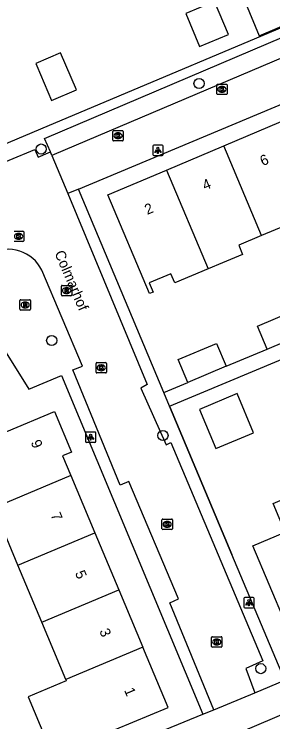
# Model space of a CAD drawing. Extents: x 157767 to 159171, y 387842 to 389425.
# Drawn here: x 158881 to 158906, y 388111.6 to 388179.9 of the extents above; entities that cross this region are included whole.
import ezdxf

# ---------------------------------------------------------------- set-up
doc = ezdxf.new("R2010")
doc.units = 0
for name, color, linetype in [('IMGEO_Boom', 7, 'Continuous'), ('IMGEO_Kolk', 7, 'Continuous'), ('IMGEO_Lichtpunt', 7, 'Continuous'), ('IMGEO_Muur', 7, 'Continuous'), ('IMGEO_Openbare_ruimte_label', 7, 'Continuous'), ('IMGEO_Pand', 7, 'Continuous'), ('IMGEO_Pand_nummerreeks', 7, 'Continuous'), ('IMGEO_Rijbaan_lokaal_open', 7, 'Continuous'), ('IMGEO_Rioolput', 7, 'Continuous'), ('IMGEO_Voetpad_open', 7, 'Continuous')]:
    doc.layers.add(name, color=color, linetype=linetype)

msp = doc.modelspace()

# ---------------------------------------------------------------- linework, layer by layer
at = {"layer": 'IMGEO_Boom'}
for centre in [(158898.833, 388173.23), (158883.577, 388166.9), (158884.584, 388148.404), (158895.347, 388139.23), (158904.8, 388116.715)]:
    msp.add_circle(centre, 0.489, dxfattribs=at)
at = {"layer": 'IMGEO_Kolk'}
for p, q in [((158900.55, 388172.235), (158900.55, 388173.087)), ((158900.625, 388173.161), (158901.477, 388173.161)), ((158901.038, 388172.941), (158901.063, 388172.941)), ((158901.551, 388173.087), (158901.551, 388172.235)), ((158901.477, 388172.161), (158900.625, 388172.161)), ((158901.061, 388172.381), (158901.036, 388172.381)), ((158890.498, 388167.753), (158890.498, 388168.605)), ((158890.573, 388168.679), (158891.425, 388168.679)), ((158890.986, 388168.459), (158891.011, 388168.459)), ((158891.499, 388168.605), (158891.499, 388167.753)), ((158891.425, 388167.679), (158890.573, 388167.679)), ((158891.009, 388167.899), (158890.984, 388167.899)), ((158880.954, 388158.964), (158881.806, 388158.964)), ((158881.367, 388158.744), (158881.392, 388158.744)), ((158881.88, 388158.89), (158881.88, 388158.038)), ((158881.806, 388157.964), (158880.954, 388157.964)), ((158881.39, 388158.184), (158881.365, 388158.184)), ((158888.875, 388145.342), (158888.875, 388146.194)), ((158888.95, 388146.268), (158889.802, 388146.268)), ((158889.876, 388146.194), (158889.876, 388145.342)), ((158889.386, 388145.488), (158889.361, 388145.488)), ((158889.363, 388146.048), (158889.388, 388146.048)), ((158889.802, 388145.268), (158888.95, 388145.268)), ((158895.326, 388131.158), (158896.178, 388131.158)), ((158895.251, 388130.232), (158895.251, 388131.084)), ((158895.739, 388130.938), (158895.764, 388130.938)), ((158896.252, 388131.084), (158896.252, 388130.232)), ((158896.178, 388130.158), (158895.326, 388130.158)), ((158895.762, 388130.378), (158895.737, 388130.378)), ((158900.047, 388118.866), (158900.047, 388119.718)), ((158900.122, 388119.792), (158900.974, 388119.792)), ((158900.535, 388119.572), (158900.56, 388119.572)), ((158901.048, 388119.718), (158901.048, 388118.866)), ((158900.558, 388119.012), (158900.533, 388119.012)), ((158900.974, 388118.792), (158900.122, 388118.792))]:
    msp.add_line(p, q, dxfattribs=at)
for points in [[(158900.55, 388172.235), (158900.55, 388173.087)], [(158900.625, 388173.161), (158901.477, 388173.161)], [(158900.871, 388172.861), (158900.994, 388172.861), (158900.994, 388172.71), (158901.124, 388172.861), (158901.288, 388172.861), (158901.142, 388172.71), (158901.295, 388172.461), (158901.143, 388172.461), (158901.058, 388172.625), (158900.994, 388172.558), (158900.994, 388172.461), (158900.871, 388172.461), (158900.871, 388172.861)], [(158901.551, 388173.087), (158901.551, 388172.235)], [(158901.477, 388172.161), (158900.625, 388172.161)], [(158890.498, 388167.753), (158890.498, 388168.605)], [(158890.573, 388168.679), (158891.425, 388168.679)], [(158890.819, 388168.379), (158890.942, 388168.379), (158890.942, 388168.228), (158891.072, 388168.379), (158891.236, 388168.379), (158891.09, 388168.228), (158891.243, 388167.979), (158891.091, 388167.979), (158891.006, 388168.143), (158890.942, 388168.076), (158890.942, 388167.979), (158890.819, 388167.979), (158890.819, 388168.379)], [(158891.499, 388168.605), (158891.499, 388167.753)], [(158891.425, 388167.679), (158890.573, 388167.679)], [(158880.954, 388158.964), (158881.806, 388158.964)], [(158881.2, 388158.664), (158881.323, 388158.664), (158881.323, 388158.513), (158881.453, 388158.664), (158881.617, 388158.664), (158881.471, 388158.513), (158881.624, 388158.264), (158881.472, 388158.264), (158881.387, 388158.428), (158881.323, 388158.361), (158881.323, 388158.264), (158881.2, 388158.264), (158881.2, 388158.664)], [(158881.88, 388158.89), (158881.88, 388158.038)], [(158881.806, 388157.964), (158880.954, 388157.964)], [(158888.875, 388145.342), (158888.875, 388146.194)], [(158888.95, 388146.268), (158889.802, 388146.268)], [(158889.876, 388146.194), (158889.876, 388145.342)], [(158889.196, 388145.968), (158889.319, 388145.968), (158889.319, 388145.817), (158889.449, 388145.968), (158889.613, 388145.968), (158889.467, 388145.817), (158889.62, 388145.568), (158889.468, 388145.568), (158889.383, 388145.732), (158889.319, 388145.665), (158889.319, 388145.568), (158889.196, 388145.568), (158889.196, 388145.968)], [(158889.802, 388145.268), (158888.95, 388145.268)], [(158895.326, 388131.158), (158896.178, 388131.158)], [(158895.251, 388130.232), (158895.251, 388131.084)], [(158895.572, 388130.858), (158895.695, 388130.858), (158895.695, 388130.707), (158895.825, 388130.858), (158895.989, 388130.858), (158895.843, 388130.707), (158895.996, 388130.458), (158895.844, 388130.458), (158895.759, 388130.622), (158895.695, 388130.555), (158895.695, 388130.458), (158895.572, 388130.458), (158895.572, 388130.858)], [(158896.252, 388131.084), (158896.252, 388130.232)], [(158896.178, 388130.158), (158895.326, 388130.158)], [(158900.047, 388118.866), (158900.047, 388119.718)], [(158900.122, 388119.792), (158900.974, 388119.792)], [(158901.048, 388119.718), (158901.048, 388118.866)], [(158900.368, 388119.492), (158900.491, 388119.492), (158900.491, 388119.341), (158900.621, 388119.492), (158900.785, 388119.492), (158900.639, 388119.341), (158900.792, 388119.092), (158900.64, 388119.092), (158900.555, 388119.256), (158900.491, 388119.189), (158900.491, 388119.092), (158900.368, 388119.092), (158900.368, 388119.492)], [(158900.974, 388118.792), (158900.122, 388118.792)]]:
    msp.add_lwpolyline(points, dxfattribs=at)
for centre, start, end in [((158900.627, 388173.085), 91.55205, 178.44795), ((158900.627, 388173.085), 91.55205, 178.44795), ((158901.475, 388173.085), 1.55205, 88.44795), ((158901.475, 388173.085), 1.55205, 88.44795), ((158900.627, 388172.237), 181.55205, 268.44795), ((158900.627, 388172.237), 181.55205, 268.44795), ((158901.475, 388172.237), 271.55205, 358.44795), ((158901.475, 388172.237), 271.55205, 358.44795), ((158890.575, 388168.603), 91.55205, 178.44795), ((158890.575, 388168.603), 91.55205, 178.44795), ((158891.423, 388168.603), 1.55205, 88.44795), ((158891.423, 388168.603), 1.55205, 88.44795), ((158890.575, 388167.755), 181.55205, 268.44795), ((158890.575, 388167.755), 181.55205, 268.44795), ((158891.423, 388167.755), 271.55205, 358.44795), ((158891.423, 388167.755), 271.55205, 358.44795), ((158881.804, 388158.888), 1.55205, 88.44795), ((158881.804, 388158.888), 1.55205, 88.44795), ((158881.804, 388158.04), 271.55205, 358.44795), ((158881.804, 388158.04), 271.55205, 358.44795), ((158888.952, 388146.192), 91.55205, 178.44795), ((158888.952, 388146.192), 91.55205, 178.44795), ((158889.8, 388146.192), 1.55205, 88.44795), ((158889.8, 388146.192), 1.55205, 88.44795), ((158888.952, 388145.344), 181.55205, 268.44795), ((158888.952, 388145.344), 181.55205, 268.44795), ((158889.8, 388145.344), 271.55205, 358.44795), ((158889.8, 388145.344), 271.55205, 358.44795), ((158895.328, 388131.082), 91.55205, 178.44795), ((158895.328, 388131.082), 91.55205, 178.44795), ((158896.176, 388131.082), 1.55205, 88.44795), ((158896.176, 388131.082), 1.55205, 88.44795), ((158895.328, 388130.234), 181.55205, 268.44795), ((158895.328, 388130.234), 181.55205, 268.44795), ((158896.176, 388130.234), 271.55205, 358.44795), ((158896.176, 388130.234), 271.55205, 358.44795), ((158900.124, 388119.716), 91.55205, 178.44795), ((158900.124, 388119.716), 91.55205, 178.44795), ((158900.972, 388119.716), 1.55205, 88.44795), ((158900.972, 388119.716), 1.55205, 88.44795), ((158900.124, 388118.868), 181.55205, 268.44795), ((158900.124, 388118.868), 181.55205, 268.44795), ((158900.972, 388118.868), 271.55205, 358.44795), ((158900.972, 388118.868), 271.55205, 358.44795)]:
    msp.add_arc(centre, 0.0765, start, end, dxfattribs=at)
for centre, major_axis, ratio, start_param, end_param in [((158901.037, 388172.661), (-0.387, 0.002), 0.722429, 4.712389, 7.853982), ((158901.062, 388172.661), (-0.39, 0.002), 0.717154, 1.570796, 4.712389), ((158890.985, 388168.179), (-0.387, 0.002), 0.722429, 4.712389, 7.853982), ((158891.01, 388168.179), (-0.39, 0.002), 0.717154, 1.570796, 4.712389), ((158881.366, 388158.464), (-0.387, 0.002), 0.722429, 4.712389, 7.853982), ((158881.391, 388158.464), (-0.39, 0.002), 0.717154, 1.570796, 4.712389), ((158889.362, 388145.768), (-0.387, 0.002), 0.722429, 4.712389, 7.853982), ((158889.387, 388145.768), (-0.39, 0.002), 0.717154, 1.570796, 4.712389), ((158895.738, 388130.658), (-0.387, 0.002), 0.722429, 4.712389, 7.853982), ((158895.763, 388130.658), (-0.39, 0.002), 0.717154, 1.570796, 4.712389), ((158900.534, 388119.292), (-0.387, 0.002), 0.722429, 4.712389, 7.853982), ((158900.559, 388119.292), (-0.39, 0.002), 0.717154, 1.570796, 4.712389)]:
    msp.add_ellipse(centre, major_axis=major_axis, ratio=ratio, start_param=start_param, end_param=end_param, dxfattribs=at)
at = {"layer": 'IMGEO_Lichtpunt'}
for p, q in [((158894.355, 388167.175), (158894.355, 388166.368)), ((158894.355, 388167.175), (158894.355, 388166.368)), ((158895.257, 388167.27), (158894.449, 388167.27)), ((158895.257, 388167.27), (158894.449, 388167.27)), ((158895.351, 388166.368), (158895.351, 388167.175)), ((158895.351, 388166.368), (158895.351, 388167.175)), ((158894.449, 388166.274), (158895.257, 388166.274)), ((158894.449, 388166.274), (158895.257, 388166.274)), ((158887.854, 388139.472), (158887.854, 388138.665)), ((158887.854, 388139.472), (158887.854, 388138.665)), ((158888.756, 388139.567), (158887.948, 388139.567)), ((158888.756, 388139.567), (158887.948, 388139.567)), ((158888.85, 388138.665), (158888.85, 388139.472)), ((158888.85, 388138.665), (158888.85, 388139.472)), ((158887.948, 388138.571), (158888.756, 388138.571)), ((158887.948, 388138.571), (158888.756, 388138.571)), ((158903.155, 388123.48), (158903.155, 388122.673)), ((158903.155, 388123.48), (158903.155, 388122.673)), ((158904.057, 388123.575), (158903.249, 388123.575)), ((158904.057, 388123.575), (158903.249, 388123.575)), ((158904.151, 388122.673), (158904.151, 388123.48)), ((158904.151, 388122.673), (158904.151, 388123.48)), ((158903.249, 388122.579), (158904.057, 388122.579)), ((158903.249, 388122.579), (158904.057, 388122.579))]:
    msp.add_line(p, q, dxfattribs=at)
for points in [[(158894.729, 388166.839), (158894.768, 388166.811), (158894.58, 388166.549), (158894.542, 388166.576), (158894.729, 388166.839)], [(158894.831, 388166.791), (158894.878, 388166.791), (158894.878, 388166.469), (158894.831, 388166.469), (158894.831, 388166.791)], [(158894.941, 388166.811), (158894.979, 388166.838), (158895.166, 388166.576), (158895.127, 388166.548), (158894.941, 388166.811)], [(158888.228, 388139.136), (158888.267, 388139.108), (158888.079, 388138.846), (158888.041, 388138.873), (158888.228, 388139.136)], [(158888.33, 388139.088), (158888.377, 388139.088), (158888.377, 388138.766), (158888.33, 388138.766), (158888.33, 388139.088)], [(158888.44, 388139.108), (158888.478, 388139.135), (158888.665, 388138.873), (158888.626, 388138.845), (158888.44, 388139.108)], [(158903.529, 388123.144), (158903.568, 388123.116), (158903.38, 388122.854), (158903.342, 388122.881), (158903.529, 388123.144)], [(158903.631, 388123.096), (158903.678, 388123.096), (158903.678, 388122.774), (158903.631, 388122.774), (158903.631, 388123.096)], [(158903.741, 388123.116), (158903.779, 388123.143), (158903.966, 388122.881), (158903.927, 388122.853), (158903.741, 388123.116)]]:
    msp.add_lwpolyline(points, dxfattribs=at)
for centre in [(158894.854, 388166.973), (158888.353, 388139.27), (158903.654, 388123.278)]:
    msp.add_circle(centre, 0.0994, dxfattribs=at)
for centre, start, end in [((158894.449, 388167.175), 90, 180), ((158894.449, 388167.175), 90, 180), ((158895.257, 388167.175), 0, 90), ((158895.257, 388167.175), 0, 90), ((158894.449, 388166.368), 180, 270), ((158894.449, 388166.368), 180, 270), ((158895.257, 388166.368), 270, 0), ((158895.257, 388166.368), 270, 360), ((158887.948, 388139.472), 90, 180), ((158887.948, 388139.472), 90, 180), ((158888.756, 388139.472), 0, 90), ((158888.756, 388139.472), 0, 90), ((158887.948, 388138.665), 180, 270), ((158887.948, 388138.665), 180, 270), ((158888.756, 388138.665), 270, 0), ((158888.756, 388138.665), 270, 360), ((158903.249, 388123.48), 90, 180), ((158903.249, 388123.48), 90, 180), ((158904.057, 388123.48), 0, 90), ((158904.057, 388123.48), 0, 90), ((158903.249, 388122.673), 180, 270), ((158903.249, 388122.673), 180, 270), ((158904.057, 388122.673), 270, 0), ((158904.057, 388122.673), 270, 360)]:
    msp.add_arc(centre, 0.0946, start, end, dxfattribs=at)
at = {"layer": 'IMGEO_Muur'}
msp.add_lwpolyline([(158895.992, 388142.055), (158902.018, 388127.735)], dxfattribs=at)
at = {"layer": 'IMGEO_Pand'}
for points in [[(158903.309, 388181.021), (158904.65, 388177.841), (158908.366, 388179.409), (158907.024, 388182.589), (158903.309, 388181.021)], [(158897.564, 388179.993), (158898.892, 388176.812), (158901.669, 388177.971), (158900.341, 388181.153), (158897.564, 388179.993)], [(158885.44, 388176.196), (158883.046, 388175.166), (158883.146, 388174.933), (158884.581, 388171.599), (158886.975, 388172.629), (158885.44, 388176.196)], [(158901.229, 388167.214), (158906.781, 388169.556)], [(158895.679, 388164.873), (158901.229, 388167.214)], [(158904.885, 388158.545), (158901.229, 388167.214)], [(158899.706, 388155.323), (158896.485, 388153.964), (158896.11, 388154.856), (158894.008, 388153.972), (158894.384, 388153.078), (158894.043, 388152.934), (158890.015, 388162.484), (158895.679, 388164.873)], [(158895.679, 388164.873), (158899.706, 388155.323)], [(158910.809, 388160.006), (158907.498, 388158.609), (158907.128, 388159.488), (158904.885, 388158.545)], [(158904.885, 388158.545), (158902.666, 388157.612), (158903.038, 388156.728), (158901.092, 388155.908), (158899.706, 388155.323)], [(158905.404, 388147.576), (158904.47, 388149.79), (158907.957, 388151.261)], [(158905.404, 388147.576), (158908.891, 388149.047)], [(158897.737, 388144.343), (158896.803, 388146.557), (158900.526, 388148.127), (158901.46, 388145.913)], [(158901.46, 388145.913), (158897.737, 388144.343)], [(158898.865, 388141.747), (158900.462, 388137.96), (158904.101, 388139.495), (158902.504, 388143.282), (158898.865, 388141.747)], [(158878.984, 388132.253), (158876.542, 388138.069), (158880.242, 388139.623), (158884.852, 388141.558), (158886.505, 388137.619), (158885.633, 388137.253), (158886.42, 388135.378)], [(158886.42, 388135.378), (158878.984, 388132.253)], [(158886.42, 388135.378), (158888.743, 388129.846)], [(158912.899, 388123.527), (158907.177, 388121.114), (158904.027, 388128.582), (158907.17, 388129.907), (158906.004, 388132.673), (158908.584, 388133.76)], [(158881.307, 388126.721), (158878.984, 388132.253)], [(158881.307, 388126.721), (158888.743, 388129.846)], [(158888.743, 388129.846), (158891.066, 388124.314)], [(158883.63, 388121.189), (158881.307, 388126.721)], [(158883.63, 388121.189), (158891.066, 388124.314)], [(158891.066, 388124.314), (158893.389, 388118.782)], [(158885.953, 388115.657), (158883.63, 388121.189)], [(158893.389, 388118.782), (158885.953, 388115.657)], [(158891.439, 388109.144), (158890.734, 388110.822), (158895.832, 388112.963), (158893.389, 388118.782)], [(158885.953, 388115.657), (158885.999, 388115.547), (158882.316, 388114), (158883.483, 388111.225), (158885.419, 388106.615)]]:
    msp.add_lwpolyline(points, dxfattribs=at)
at = {"layer": 'IMGEO_Rijbaan_lokaal_open'}
for points in [[(158913.189, 388181.338), (158883.494, 388168.825), (158878.046, 388166.529), (158866.747, 388184.586), (158862.893, 388193.639)], [(158862.043, 388193.215), (158863.651, 388189.495), (158865.858, 388184.316), (158877.965, 388164.8), (158882.956, 388166.846), (158883.272, 388166.106), (158884.461, 388166.613)], [(158887.168, 388163.025), (158935.912, 388183.417)], [(158884.461, 388166.613), (158883.896, 388167.906), (158908.57, 388178.403), (158909.272, 388176.746), (158884.607, 388166.263)], [(158884.607, 388166.263), (158884.461, 388166.613)], [(158884.607, 388166.263), (158886.139, 388162.594)], [(158887.168, 388163.025), (158886.139, 388162.594)], [(158886.139, 388162.594), (158893.829, 388144.172), (158893.199, 388143.813), (158895.646, 388138.344), (158896.106, 388138.55), (158905.015, 388117.459), (158903.356, 388116.731), (158904.235, 388114.372)], [(158900.257, 388112.735), (158896.022, 388123.072), (158896.832, 388123.441), (158892.048, 388134.789), (158891.198, 388134.449), (158886.614, 388145.566), (158887.563, 388145.935), (158883.619, 388155.202)], [(158953.438, 388131.723), (158942.555, 388127.219), (158929.482, 388121.771), (158908.943, 388113.158), (158897.252, 388108.195)], [(158900.257, 388112.735), (158904.235, 388114.372)]]:
    msp.add_lwpolyline(points, dxfattribs=at)
msp.add_arc((158880.397, 388153.641), 3.58, 25.84674, 118.27198, dxfattribs=at)
at = {"layer": 'IMGEO_Rioolput'}
for p, q in [((158885.596, 388153.73), (158886.448, 388153.73)), ((158885.521, 388152.804), (158885.521, 388153.656)), ((158886.009, 388153.51), (158886.034, 388153.51)), ((158886.522, 388153.656), (158886.522, 388152.804)), ((158881.594, 388152.344), (158882.446, 388152.344)), ((158886.448, 388152.73), (158885.596, 388152.73)), ((158886.032, 388152.95), (158886.007, 388152.95)), ((158881.519, 388151.418), (158881.519, 388152.27)), ((158882.007, 388152.124), (158882.032, 388152.124)), ((158882.52, 388152.27), (158882.52, 388151.418)), ((158882.446, 388151.344), (158881.594, 388151.344)), ((158882.03, 388151.564), (158882.005, 388151.564))]:
    msp.add_line(p, q, dxfattribs=at)
for points in [[(158885.596, 388153.73), (158886.448, 388153.73)], [(158885.521, 388152.804), (158885.521, 388153.656)], [(158886.11, 388153.428), (158885.858, 388153.43), (158885.858, 388153.03)], [(158885.858, 388153.03), (158885.982, 388153.03), (158885.982, 388153.192), (158885.993, 388153.192)], [(158886.036, 388153.349), (158885.982, 388153.349), (158885.982, 388153.268)], [(158885.982, 388153.268), (158886.034, 388153.268)], [(158886.04, 388153.163), (158886.111, 388153.03), (158886.251, 388153.03), (158886.186, 388153.156)], [(158886.522, 388153.656), (158886.522, 388152.804)], [(158881.594, 388152.344), (158882.446, 388152.344)], [(158886.448, 388152.73), (158885.596, 388152.73)], [(158881.519, 388151.418), (158881.519, 388152.27)], [(158882.108, 388152.042), (158881.856, 388152.044), (158881.856, 388151.644)], [(158881.856, 388151.644), (158881.98, 388151.644), (158881.98, 388151.806), (158881.991, 388151.806)], [(158882.034, 388151.963), (158881.98, 388151.963), (158881.98, 388151.882)], [(158881.98, 388151.882), (158882.032, 388151.882)], [(158882.038, 388151.777), (158882.109, 388151.644), (158882.249, 388151.644), (158882.184, 388151.77)], [(158882.52, 388152.27), (158882.52, 388151.418)], [(158882.446, 388151.344), (158881.594, 388151.344)]]:
    msp.add_lwpolyline(points, dxfattribs=at)
for centre, radius, start, end in [((158885.598, 388153.654), 0.0765, 91.55205, 178.44795), ((158885.598, 388153.654), 0.0765, 91.55205, 178.44795), ((158886.446, 388153.654), 0.0765, 1.55205, 88.44795), ((158886.446, 388153.654), 0.0765, 1.55205, 88.44795), ((158885.992, 388153.139), 0.0533, 26.02933, 88.69889), ((158886.018, 388153.457), 0.19, 274.7715, 282.96867), ((158886.042, 388153.253), 0.0964, 77.00612, 93.18647), ((158886.056, 388153.31), 0.0378, 276.66336, 79.67722), ((158886.109, 388153.318), 0.109, 350.36119, 89.41601), ((158886.107, 388153.318), 0.112, 277.58423, 350.98172), ((158886.091, 388153.103), 0.108, 29.51342, 73.79051), ((158881.596, 388152.268), 0.0765, 91.55205, 178.44795), ((158881.596, 388152.268), 0.0765, 91.55205, 178.44795), ((158882.444, 388152.268), 0.0765, 1.55205, 88.44795), ((158882.444, 388152.268), 0.0765, 1.55205, 88.44795), ((158885.598, 388152.806), 0.0765, 181.55205, 268.44795), ((158885.598, 388152.806), 0.0765, 181.55205, 268.44795), ((158886.446, 388152.806), 0.0765, 271.55205, 358.44795), ((158886.446, 388152.806), 0.0765, 271.55205, 358.44795), ((158881.99, 388151.753), 0.0533, 26.02933, 88.69889), ((158882.016, 388152.071), 0.19, 274.7715, 282.96867), ((158882.04, 388151.867), 0.0964, 77.00612, 93.18647), ((158882.054, 388151.924), 0.0378, 276.66336, 79.67722), ((158882.107, 388151.932), 0.109, 350.36119, 89.41601), ((158882.105, 388151.932), 0.112, 277.58423, 350.98172), ((158882.089, 388151.717), 0.108, 29.51342, 73.79051), ((158881.596, 388151.42), 0.0765, 181.55205, 268.44795), ((158881.596, 388151.42), 0.0765, 181.55205, 268.44795), ((158882.444, 388151.42), 0.0765, 271.55205, 358.44795), ((158882.444, 388151.42), 0.0765, 271.55205, 358.44795)]:
    msp.add_arc(centre, radius, start, end, dxfattribs=at)
for centre, major_axis, ratio, start_param, end_param in [((158886.008, 388153.23), (-0.387, 0.002), 0.722429, 4.712389, 7.853982), ((158886.033, 388153.23), (-0.39, 0.002), 0.717154, 1.570796, 4.712389), ((158882.006, 388151.844), (-0.387, 0.002), 0.722429, 4.712389, 7.853982), ((158882.031, 388151.844), (-0.39, 0.002), 0.717154, 1.570796, 4.712389)]:
    msp.add_ellipse(centre, major_axis=major_axis, ratio=ratio, start_param=start_param, end_param=end_param, dxfattribs=at)
at = {"layer": 'IMGEO_Voetpad_open'}
for points in [[(158852.533, 388185.971), (158854.016, 388186.593), (158855.965, 388185.942), (158856.305, 388185.398), (158882.366, 388143.71), (158885.534, 388145.037), (158899.188, 388112.326)], [(158895.437, 388143.373), (158887.168, 388163.025)], [(158895.992, 388142.055), (158909.468, 388147.684)], [(158901.46, 388145.913), (158905.404, 388147.576)], [(158895.437, 388143.373), (158897.737, 388144.343)], [(158895.992, 388142.055), (158895.437, 388143.373)], [(158907.126, 388115.595), (158902.018, 388127.735), (158895.992, 388142.055)], [(158904.235, 388114.372), (158907.126, 388115.595)], [(158899.188, 388112.326), (158900.257, 388112.735)], [(158891.439, 388109.144), (158899.188, 388112.326)]]:
    msp.add_lwpolyline(points, dxfattribs=at)

# ---------------------------------------------------------------- texts
at = {"layer": 'IMGEO_Openbare_ruimte_label'}
msp.add_text('Colmarhof', height=1, rotation=293.07822, dxfattribs=at).set_placement((158884.842, 388156.855))
at = {"layer": 'IMGEO_Pand_nummerreeks'}
for s, rotation, p in [('6', 22.86951, (158904.985, 388165.238)), ('4', 22.86951, (158899.405, 388162.885)), ('2', 22.86951, (158893.824, 388160.531)), ('9', 292.76534, (158882.547, 388138.572)), ('7', 292.77679, (158884.466, 388131.56)), ('5', 292.77679, (158886.819, 388125.956)), ('3', 292.77679, (158889.172, 388120.352)), ('1', 292.77679, (158891.569, 388114.643))]:
    msp.add_text(s, height=1, rotation=rotation, dxfattribs=at).set_placement(p)

doc.saveas('drawing.dxf')
